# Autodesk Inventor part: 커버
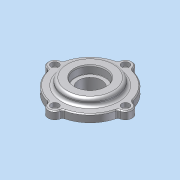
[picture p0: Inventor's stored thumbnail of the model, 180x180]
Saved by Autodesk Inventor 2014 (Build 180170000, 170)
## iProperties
Company: 한국ATC센터
Created: 2015-03
Part Number: 커버
Document SubType Name: Modeling
Designer: KYOUNG IL JANG
Density: 1 g/cm^3
Material: 일반
Appearance: 기본값
Author: KYOUNG IL JANG
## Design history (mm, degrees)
sketch "스케치1"
  geometry: C1 r 1.621 at (0, 6.75) reference; C2 r 1.621 at (-37, -30.25) reference; C3 r 1.621 at (0, -67.25) reference; C4 r 1.621 at (37, -30.25) reference; C5 r 10 at (0, -30.25) reference; C6 r 12 at (0, -30.25); C7 r 24.5 at (0, -30.25) reference; A1 r 3 centre (-38.77, -20.408) between (-38.239, -23.361) and (-35.862, -21.146) reference; A2 r 7 centre (-37, -30.25) between (-38.239, -23.361) and (-38.239, -37.139) reference; A3 r 3 centre (-38.77, -40.092) between (-35.862, -39.354) and (-38.239, -37.139) reference; A4 r 37 centre (0, -30.25) between (-35.862, -39.354) and (-9.104, -66.113) reference; A5 r 3 centre (-9.842, -69.02) between (-6.889, -68.489) and (-9.104, -66.113) reference; A6 r 7 centre (0, -67.25) between (-6.889, -68.489) and (6.889, -68.489) reference; A7 r 3 centre (9.842, -69.02) between (9.104, -66.112) and (6.889, -68.489) reference; A8 r 37 centre (0, -30.25) between (9.104, -66.112) and (35.863, -39.354) reference; A9 r 3 centre (38.77, -40.092) between (38.239, -37.139) and (35.863, -39.354) reference; A10 r 7 centre (37, -30.25) between (38.239, -37.139) and (38.239, -23.361) reference; A11 r 3 centre (38.77, -20.408) between (35.863, -21.146) and (38.239, -23.361) reference; A12 r 37 centre (0, -30.25) between (35.863, -21.146) and (9.104, 5.612) reference; A13 r 3 centre (9.842, 8.52) between (6.889, 7.989) and (9.104, 5.612) reference; A14 r 7 centre (0, 6.75) between (6.889, 7.989) and (-6.889, 7.989) reference; A15 r 3 centre (-9.842, 8.52) between (-9.104, 5.612) and (-6.889, 7.989) reference; A16 r 37 centre (0, -30.25) between (-9.104, 5.612) and (-35.862, -21.146) reference; 1 further point
  constraints: 1 centre point, 1 coincident
  dimensions: "d2" = 2 radial gap between concentric circles of C6 C5
extrude "돌출1" new body sketch "스케치1" distance "d0" = 8; taper "d1" = 0 deg
sketch "스케치2"
  geometry: C1 r 23.5 at (0, -30.25) reference; C2 r 12 at (0, -30.25) reference; 1 further point
extrude "돌출2" join sketch "스케치2" distance "d4" = 5; taper "d5" = 0 deg
sketch "스케치3"
  geometry: C1 r 23.5 at (0, 0) reference; C2 r 20.5 at (0, 0); 1 further point
  constraints: 1 centre point
  dimensions: "d6" = 3 radial gap between concentric circles of C2 C1
node "작업 평면1"
extrude "돌출3" join sketch "스케치3" stored distance "d7" = 5; taper "d8" = 0 deg
fillet "모깎기1" dims "d9" = 3
sketch "스케치4"
  geometry: C1 r 12 at (0, -30.25) reference; C2 r 27 at (0, -30.25); 1 further point
  constraints: 1 centre point
  dimensions: "d10" = 15 radial gap between concentric circles of C1 C2
extrude "돌출4" join sketch "스케치4" distance "d11" = 7; taper "d12" = 0 deg
fillet "모깎기2" dims "d13" = 3
chamfer "모따기1" distance "d14" = 1; stored, may be unused: second distance "d15" = 2, angle "d16" = 45 deg
node "작업점1"
  node "작업축1"
chamfer "모따기2" distance "d24" = 1; stored, may be unused: second distance "d25" = 2, angle "d26" = 45 deg
hole "구멍6" diameter "d43" = 4.5; stored, may be unused: countersink angle "d47" = 90 deg, drill point angle "d49" = 118 deg; dims "d41" = 10, "d42" = 10, "d44" = 6, "d45" = 8, "d46" = 4.4, "d48" = 8
sketch "스케치8"
  geometry: C1 r 12 at (0, 0) reference; C2 r 16 at (0, 0); 1 further point
  constraints: 1 centre point, 1 coincident
  dimensions: "d53" = 32 diameter of C2
extrude "돌출5" cut sketch "스케치8" distance "d54" = 8.3; taper "d55" = 0 deg
fillet "모깎기3" dims "d56" = 0.3
chamfer "모따기3" distance "d57" = 1.2; stored, may be unused: second distance "d58" = 2, angle "d59" = 30 deg
node "솔리드1"
pattern_circular "원형 패턴1" dims angle "d51" = 360 deg
node "참조1"
node "참조2"
